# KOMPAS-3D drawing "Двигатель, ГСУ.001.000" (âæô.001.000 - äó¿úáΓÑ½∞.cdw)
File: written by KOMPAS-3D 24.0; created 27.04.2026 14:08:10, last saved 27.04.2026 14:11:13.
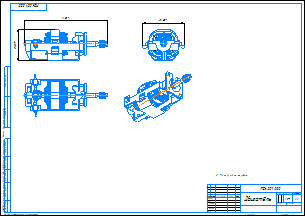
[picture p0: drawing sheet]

Document properties: Автор: User7; Форматы листов документа: A4; Полное имя файла: ГСУ.001.000 - Двигатель.spw; Масса: 0.572265; Наименование: Двигатель; Количество листов документа: 1

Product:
- Component [detail]: Рама двигателя  | designation ГСУ.001.001  | qty 1  | pos. 4  | Масса: 0.221971; Автор: User7; source file: ГСУ.001.001 - Рама двигателя.m3d
- Component [assembly]: Ротор  | designation ГСУ.001.100  | qty 1  | pos. 1  | Масса: 0.279522; Автор: User7; source file: ГСУ.001.100 - Ротор.a3d
- Component [detail]: Обмотка  | designation ГСУ.001.009  | qty 2  | pos. 12  | Масса: 0.009726; Автор: User7; source file: ГСУ.001.009 - Обмотка.m3d
- Component [detail]: Держатель статора  | designation ГСУ.001.012  | qty 2  | pos. 15  | Масса: 0.004314; Автор: User7; source file: ГСУ.001.012 - Держатель статора.m3d
- Component [detail]: Пластина держателя пружин  | designation ГСУ.001.011  | qty 1  | pos. 14  | Масса: 0.000005; Автор: User7; source file: ГСУ.001.011 - Пластина держателя пружин.m3d
- Component [detail]: Пластина держателя втулок ротора  | designation ГСУ.001.013  | qty 1  | pos. 16  | Масса: 0.000957; Автор: User7; source file: ГСУ.001.013 - Пластина держателя втулок ротора.m3d
- Component [detail]: Уплотнитель  | designation ГСУ.001.007  | qty 1  | pos. 10  | Масса: 0.011541; Автор: User7; source file: ГСУ.001.007 - Уплотнитель.m3d
- Component [detail]: Основание статора  | designation ГСУ.001.002  | qty 1  | pos. 5  | Масса: 0.01025; Автор: User7; source file: ГСУ.001.002 - Основание статора.m3d
- Component [detail]: Держатель щеток  | designation ГСУ.001.003  | qty 2  | pos. 6  | Масса: 0.006051; Автор: User7; source file: ГСУ.001.003 - Держатель щеток.m3d
- Component [detail]: Щетка  | designation ГСУ.001.004  | qty 2  | pos. 7  | Масса: 0.001131; Автор: User7; source file: ГСУ.001.004 - Щетка.m3d
- Component [detail]: Пластина  | designation ГСУ.001.005  | qty 1  | pos. 8  | Масса: 0.002726; Автор: User7; source file: ГСУ.001.005 - Пластина.m3d
- Component [detail]: Пластинка  | designation ГСУ.001.006  | qty 1  | pos. 9  | Масса: 0.001875; Автор: User7; source file: ГСУ.001.006 - Пластинка.m3d
- Component [detail]: Пружина  | designation ГСУ.001.008  | qty 2  | pos. 11  | Масса: 0.00001; Автор: User7; source file: ГСУ.001.008 - Пружина.m3d
- Component [detail]: Резистор  | designation ГСУ.001.010  | qty 2  | pos. 13  | Масса: 0.000476; Автор: User7; source file: ГСУ.001.010 - Резистор.m3d
- Part/product: Двигатель  | designation ГСУ.001.000
    Масса: 0.572265
    Форматы листов документа: A4
    source file: ГСУ.001.000 - Двигатель.spw

Views: Сечение проволоки, Сечение проволоки 2
Referenced files in C:\Users\User7\Desktop\олимп\: ГСУ.001.001 - Рама двигателя.m3d, ГСУ.001.100 - Ротор.a3d, ГСУ.001.009 - Обмотка.m3d, ГСУ.001.012 - Держатель статора.m3d, ГСУ.001.011 - Пластина держателя пружин.m3d, ГСУ.001.013 - Пластина держателя втулок ротора.m3d, ГСУ.001.007 - Уплотнитель.m3d, ГСУ.001.002 - Основание статора.m3d, ГСУ.001.003 - Держатель щеток.m3d, ГСУ.001.004 - Щетка.m3d, ГСУ.001.005 - Пластина.m3d, ГСУ.001.006 - Пластинка.m3d, ГСУ.001.008 - Пружина.m3d, ГСУ.001.010 - Резистор.m3d, ГСУ.001.000 - Двигатель.cdw, ГСУ.001.102 - Вал ротора.m3d, ГСУ.001.104 - Пропеллер.m3d, ГСУ.001.105 - Коллектор.m3d, ГСУ.001.106 - Шайба.m3d, ГСУ.001.107 - Втулка.m3d, ГСУ.001.108 - Пластина.m3d, ГСУ.001.109 - Обмотка.m3d, ГСУ.001.101 - Звездочка.m3d, ГСУ.001.103 - Шестерня.m3d, ГСУ.001.110 - Пластина.m3d, ГСУ.001.000 - Двигатель.a3d
Referenced files in C:\Program Files\ASCON\KOMPAS-3D v21\Libs\PARTLib\DATA\vault\Methods\Kompas\3D\: PLib_Nut_OST92_900.m3d
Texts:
  Программные изделия  и базы данных
  Принадлежности
  Приспособления
  Упаковка
  ГСУ.001.001
  Рама двигателя
  ГСУ.001.100
  Ротор
  ГСУ.001.009
  Обмотка
  ГСУ.001.012
  Держатель статора
  ГСУ.001.011
  Пластина держателя пружин
  ГСУ.001.013
  Пластина держателя втулок ротора
  ГСУ.001.007
  Уплотнитель
  ГСУ.001.002
  Основание статора
  ГСУ.001.003
  Держатель щеток
  ГСУ.001.004
  Щетка
  ГСУ.001.005
  Пластина
  ГСУ.001.006
  Пластинка
  ГСУ.001.008
  Пружина
  ГСУ.001.010
  Резистор
  ГСУ.001.000
  Двигатель
  ГСУ.001.001 Рама двигателя
  Вал ротора
  ГСУ.001.102
  ГСУ.001.102 Вал ротора
  Пропеллер
  ГСУ.001.104
  ГСУ.001.104 Пропеллер
  Коллектор
  ГСУ.001.105
  ГСУ.001.105 Коллектор
  Шайба
  ГСУ.001.106
  ГСУ.001.106 Шайба
  Втулка
  ГСУ.001.107
  ГСУ.001.107 Втулка
  ГСУ.001.108
  ГСУ.001.108 Пластина
  ГСУ.001.109
  ГСУ.001.109 Обмотка
  Звездочка
  ГСУ.001.101
  ГСУ.001.101 Звездочка
  Гайка М4-6H ГОСТ 15523-70
  Шестеренка
  ГСУ.001.103
  ГСУ.001.103 Шестеренка
  ГСУ.001.110
  ГСУ.001.110 Пластина
  ГСУ.001.100 Ротор
  ГСУ.001.009 Обмотка
  ГСУ.001.012 Держатель статора
  ГСУ.001.011 Пластина держателя пружин
  ГСУ.001.013 Пластина держателя втулок ротора
  ГСУ.001.007 Уплотнитель
  ГСУ.001.002 Основание статора
  ГСУ.001.003 Держатель щеток
  ГСУ.001.004 Щетка
  ГСУ.001.005 Пластина
  ГСУ.001.006 Пластинка
  Спираль рабочих витков
  Спираль первого поджатого витка
  Спираль второго поджатого витка
  ГСУ.001.008 Пружина
  ГСУ.001.010 Резистор
  ГСУ.001.000 Двигатель
Dimensions and other numbers on the sheet: 4; 1; 12; 2; 15; 14; 16; 10; 5; 6; 7; 8; 9; 11; 13; 1:1; 0; 0,57

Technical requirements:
  *Размеры для справок.
  GOST Type AU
